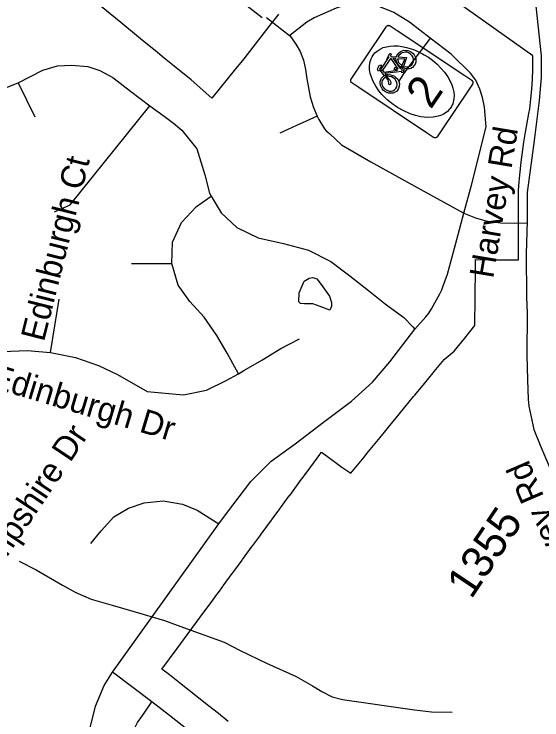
# Model space of a CAD drawing. Extents: x 1715610 to 1720914, y 798298 to 802505.
# Drawn here: x 1715843.1 to 1715888.3, y 799772 to 799832.4 of the extents above; entities that cross this region are included whole.
import ezdxf

# ---------------------------------------------------------------- set-up
doc = ezdxf.new("R2010")
doc.units = 0
doc.layers.add('Default', color=7, linetype='Continuous')

msp = doc.modelspace()

# ---------------------------------------------------------------- linework, layer by layer
at = {"layer": 'Default'}
for p, q in [((1715843.498, 799826.51), (1715844.92, 799823.586)), ((1715853.189, 799811.031), (1715856.623, 799811.039)), ((1715846.258, 799803.408), (1715846.988, 799807.974)), ((1715851.549, 799776.047), (1715860.659, 799788.734)), ((1715854.933, 799773.497), (1715851.549, 799776.047))]:
    msp.add_line(p, q, dxfattribs=at)
for points in [[(1715876.559, 799852.158), (1715873.018, 799854.904), (1715871.602, 799856.072), (1715871.096, 799856.41), (1715870.539, 799856.563), (1715870.048, 799856.378), (1715869.015, 799855.163), (1715864.188, 799848.936), (1715859.918, 799843.325), (1715857.646, 799840.515), (1715856.993, 799839.629), (1715856.823, 799839.026), (1715856.969, 799838.292), (1715857.158, 799837.776), (1715857.596, 799837.336), (1715858.861, 799836.269), (1715862.057, 799833.917), (1715864.379, 799832.097)], [(1715887.585, 799834.985), (1715887.96, 799831.478), (1715888.231, 799828.832), (1715888.24, 799826.949), (1715888.059, 799825.001), (1715887.645, 799821.58), (1715887.043, 799817.108), (1715887.035, 799814.677), (1715886.966, 799811.853), (1715886.98, 799808.164), (1715887.054, 799806.818), (1715887.014, 799803.184), (1715887.069, 799801.068), (1715887.121, 799799.414), (1715887.192, 799798.806), (1715887.621, 799796.808), (1715888.149, 799795.48), (1715889.133, 799793.201), (1715891.599, 799788.185)], [(1715886.642, 799820.577), (1715886.762, 799821.426), (1715886.899, 799822.273), (1715887.191, 799823.877), (1715887.258, 799824.293), (1715887.37, 799825.131), (1715887.452, 799825.969), (1715887.505, 799826.814), (1715887.529, 799827.655), (1715887.52, 799828.81), (1715880.178, 799834.08)], [(1715886.642, 799820.577), (1715886.762, 799821.426), (1715886.899, 799822.273), (1715887.191, 799823.877), (1715887.258, 799824.293), (1715887.37, 799825.131), (1715887.452, 799825.969), (1715887.505, 799826.814), (1715887.529, 799827.655), (1715887.52, 799828.81), (1715880.178, 799834.08)], [(1715865.775, 799832.394), (1715865.709, 799832.311), (1715865.027, 799831.433), (1715862.788, 799828.567), (1715862.536, 799828.245), (1715862.075, 799827.696), (1715860.067, 799825.183), (1715858.278, 799826.763), (1715856.833, 799827.94), (1715855.984, 799828.632), (1715855.408, 799829.1), (1715853.96, 799830.281), (1715852.268, 799831.66), (1715850.585, 799833.031)], [(1715865.775, 799832.394), (1715865.709, 799832.311), (1715865.027, 799831.433), (1715862.788, 799828.567), (1715862.536, 799828.245), (1715862.075, 799827.696), (1715860.067, 799825.183), (1715858.278, 799826.763), (1715856.833, 799827.94), (1715855.984, 799828.632), (1715855.408, 799829.1), (1715853.96, 799830.281), (1715852.268, 799831.66), (1715850.585, 799833.031)], [(1715878.748, 799830.326), (1715876.976, 799831.699), (1715875.637, 799832.526), (1715874.152, 799833.131), (1715873.227, 799833.256), (1715872.14, 799833.254), (1715871.393, 799833.126), (1715870.693, 799832.911), (1715868.815, 799832.08), (1715868.19, 799831.713), (1715866.72, 799830.548)], [(1715864.75, 799832.102), (1715866.702, 799830.573), (1715866.72, 799830.548)], [(1715866.72, 799830.548), (1715867.258, 799829.831), (1715867.629, 799829.184), (1715867.914, 799828.437), (1715868.071, 799827.645), (1715868.199, 799826.843), (1715868.339, 799826.065), (1715868.486, 799825.312), (1715868.757, 799824.385), (1715869.066, 799823.662)], [(1715878.748, 799830.326), (1715878.345, 799829.778), (1715877.811, 799829.072), (1715877.353, 799828.489), (1715876.892, 799827.875), (1715876.466, 799827.264), (1715876.064, 799826.643)], [(1715881.627, 799815.333), (1715882.276, 799817.751), (1715883.539, 799822.736), (1715883.392, 799824.424), (1715883.231, 799825.239), (1715883.005, 799825.975), (1715882.643, 799826.725), (1715882.193, 799827.33), (1715880.533, 799828.955), (1715878.748, 799830.326)], [(1715843.498, 799826.51), (1715845.61, 799827.603), (1715846.865, 799827.957), (1715848.037, 799828.027), (1715849.445, 799827.902), (1715850.482, 799827.555), (1715851.585, 799826.954), (1715853.101, 799825.802), (1715854.741, 799824.547)], [(1715838.111, 799825.072), (1715840.042, 799825.389), (1715842.115, 799825.964), (1715843.498, 799826.51)], [(1715846.609, 799815.458), (1715847.925, 799816.059), (1715854.741, 799824.547)], [(1715854.741, 799824.547), (1715855.99, 799823.652), (1715856.769, 799823.052), (1715857.483, 799822.457), (1715858.768, 799820.857), (1715859.464, 799818.632), (1715859.865, 799817.044), (1715860.014, 799816.794)], [(1715869.066, 799823.662), (1715868.12, 799823.212), (1715867.296, 799822.838), (1715866.556, 799822.502), (1715865.892, 799822.197)], [(1715869.066, 799823.662), (1715869.214, 799823.36), (1715869.692, 799822.559), (1715869.836, 799822.397), (1715870.121, 799822.154), (1715871.155, 799821.2), (1715873.651, 799819.739), (1715876.813, 799817.985), (1715879.345, 799816.589), (1715881.627, 799815.333)], [(1715861.464, 799771.825), (1715860.625, 799772.485), (1715859.779, 799773.156), (1715858.946, 799773.811), (1715858.112, 799774.471), (1715857.279, 799775.13), (1715856.433, 799775.797), (1715855.793, 799776.305), (1715856.438, 799777.181), (1715857.084, 799778.061), (1715858.967, 799780.625), (1715859.067, 799780.757), (1715860.139, 799782.216), (1715860.405, 799782.577), (1715860.623, 799782.873), (1715860.988, 799783.375), (1715861.026, 799783.428), (1715861.81, 799784.493), (1715861.849, 799784.546), (1715862, 799784.752), (1715862.192, 799785.013), (1715862.651, 799785.638), (1715862.69, 799785.69), (1715863.524, 799786.824), (1715863.561, 799786.874), (1715864.159, 799787.687), (1715864.336, 799787.929), (1715864.373, 799787.98), (1715865.168, 799789.06), (1715865.206, 799789.113), (1715865.907, 799790.067), (1715865.944, 799790.117), (1715866.686, 799791.126), (1715866.711, 799791.161), (1715866.723, 799791.176), (1715867.745, 799792.566), (1715867.782, 799792.617), (1715868.526, 799793.627), (1715869.304, 799794.687), (1715869.343, 799794.739), (1715869.443, 799794.871), (1715869.955, 799794.499), (1715871.189, 799793.601), (1715871.94, 799793.069), (1715873.082, 799794.461), (1715873.33, 799794.763), (1715874.455, 799796.137), (1715875.556, 799797.481), (1715875.724, 799797.685), (1715876.572, 799798.721), (1715877.32, 799799.633), (1715877.419, 799799.754), (1715878.244, 799800.759), (1715878.985, 799801.663), (1715879.088, 799801.79), (1715879.933, 799802.821), (1715880.807, 799803.528), (1715881.696, 799804.651), (1715882.556, 799805.737), (1715882.559, 799806.003), (1715882.586, 799807.843), (1715882.629, 799810.91), (1715882.635, 799811.367), (1715884.007, 799811.355), (1715886.305, 799811.335), (1715886.315, 799817.298), (1715886.366, 799818.017), (1715886.443, 799818.872), (1715886.535, 799819.726), (1715886.642, 799820.577)], [(1715861.464, 799771.825), (1715860.625, 799772.485), (1715859.779, 799773.156), (1715858.946, 799773.811), (1715858.112, 799774.471), (1715857.279, 799775.13), (1715856.433, 799775.797), (1715855.793, 799776.305), (1715856.438, 799777.181), (1715857.084, 799778.061), (1715858.967, 799780.625), (1715859.067, 799780.757), (1715860.139, 799782.216), (1715860.405, 799782.577), (1715860.623, 799782.873), (1715860.988, 799783.375), (1715861.026, 799783.428), (1715861.81, 799784.493), (1715861.849, 799784.546), (1715862, 799784.752), (1715862.192, 799785.013), (1715862.651, 799785.638), (1715862.69, 799785.69), (1715863.524, 799786.824), (1715863.561, 799786.874), (1715864.159, 799787.687), (1715864.336, 799787.929), (1715864.373, 799787.98), (1715865.168, 799789.06), (1715865.206, 799789.113), (1715865.907, 799790.067), (1715865.944, 799790.117), (1715866.686, 799791.126), (1715866.711, 799791.161), (1715866.723, 799791.176), (1715867.745, 799792.566), (1715867.782, 799792.617), (1715868.526, 799793.627), (1715869.304, 799794.687), (1715869.343, 799794.739), (1715869.443, 799794.871), (1715869.955, 799794.499), (1715871.189, 799793.601), (1715871.94, 799793.069), (1715873.082, 799794.461), (1715873.33, 799794.763), (1715874.455, 799796.137), (1715875.556, 799797.481), (1715875.724, 799797.685), (1715876.572, 799798.721), (1715877.32, 799799.633), (1715877.419, 799799.754), (1715878.244, 799800.759), (1715878.985, 799801.663), (1715879.088, 799801.79), (1715879.933, 799802.821), (1715880.807, 799803.528), (1715881.696, 799804.651), (1715882.556, 799805.737), (1715882.559, 799806.003), (1715882.586, 799807.843), (1715882.629, 799810.91), (1715882.635, 799811.367), (1715884.007, 799811.355), (1715886.305, 799811.335), (1715886.315, 799817.298), (1715886.366, 799818.017), (1715886.443, 799818.872), (1715886.535, 799819.726), (1715886.642, 799820.577)], [(1715856.623, 799811.039), (1715856.687, 799812.861), (1715857.462, 799814.541), (1715858.748, 799815.911), (1715859.729, 799816.596), (1715860.014, 799816.794)], [(1715860.014, 799816.794), (1715860.857, 799815.376), (1715862.191, 799814.107), (1715864.021, 799813.245), (1715866.187, 799812.738), (1715868.333, 799812.168), (1715870.235, 799811.209), (1715871.873, 799809.986), (1715873.467, 799808.723), (1715874.899, 799807.568), (1715876.493, 799806.409), (1715877.248, 799805.616), (1715877.433, 799805.41)], [(1715877.433, 799805.41), (1715878.366, 799806.455), (1715878.631, 799806.787), (1715878.862, 799807.153), (1715879.577, 799808.435), (1715879.748, 799808.784), (1715879.84, 799809.027), (1715880.218, 799810.119), (1715881.019, 799813.093), (1715881.627, 799815.333)], [(1715881.627, 799815.333), (1715882.627, 799814.932), (1715883.508, 799814.682), (1715884.756, 799814.511), (1715886, 799814.496), (1715886.982, 799814.526)], [(1715862.333, 799801.6), (1715861.365, 799803.347), (1715860.477, 799804.861), (1715859.404, 799806.433), (1715858.184, 799807.789), (1715857.183, 799809.169), (1715856.623, 799811.039)], [(1715870.166, 799807.043), (1715869.325, 799807.354), (1715868.69, 799807.58), (1715868.001, 799807.574), (1715867.652, 799807.604), (1715867.496, 799807.762), (1715867.54, 799808.521), (1715867.951, 799809.508), (1715868.399, 799809.777), (1715868.702, 799809.837), (1715869.039, 799809.713), (1715869.406, 799809.247), (1715869.834, 799808.639), (1715870.131, 799808.225), (1715870.295, 799807.692), (1715870.293, 799807.382), (1715870.166, 799807.043)], [(1715870.166, 799807.043), (1715869.325, 799807.354), (1715868.69, 799807.58), (1715868.001, 799807.574), (1715867.652, 799807.604), (1715867.496, 799807.762), (1715867.54, 799808.521), (1715867.951, 799809.508), (1715868.399, 799809.777), (1715868.702, 799809.837), (1715869.039, 799809.713), (1715869.406, 799809.247), (1715870.131, 799808.225), (1715870.295, 799807.692), (1715870.293, 799807.382), (1715870.166, 799807.043)], [(1715860.659, 799788.734), (1715861.319, 799789.618), (1715863.392, 799792.359), (1715865.147, 799794.106), (1715867.199, 799795.582), (1715869.609, 799797.436), (1715872.02, 799799.232), (1715873.819, 799800.864), (1715875.28, 799802.615), (1715877.433, 799805.41)], [(1715862.333, 799801.6), (1715862.81, 799801.873), (1715864.351, 799802.758), (1715865.952, 799803.745), (1715867.565, 799804.576)], [(1715838.243, 799802.606), (1715838.311, 799802.626), (1715840.122, 799803.168), (1715842.183, 799803.499), (1715844.268, 799803.572), (1715846.258, 799803.408)], [(1715846.258, 799803.408), (1715848.387, 799802.974), (1715850.36, 799802.298), (1715851.977, 799801.534), (1715854.538, 799800.065), (1715857.628, 799799.783), (1715859.602, 799800.199), (1715861.279, 799801.013), (1715862.333, 799801.6)], [(1715849.714, 799787.057), (1715850.578, 799788.153), (1715851.68, 799789.34), (1715852.936, 799790.076), (1715854.258, 799790.532), (1715855.893, 799790.707), (1715857.561, 799790.416), (1715858.795, 799789.901), (1715860.659, 799788.734)], [(1715843.566, 799785.536), (1715845.02, 799784.81), (1715847.272, 799783.479), (1715848.422, 799782.849), (1715849.72, 799782.281), (1715851.537, 799781.778), (1715853.294, 799781.263), (1715856.011, 799780.458), (1715857.959, 799779.761), (1715861.121, 799778.605), (1715862.475, 799777.887), (1715864.745, 799776.813), (1715867.278, 799775.66), (1715868.68, 799774.861), (1715869.46, 799774.382), (1715870.36, 799773.924), (1715871.251, 799773.687), (1715877.398, 799772.809), (1715878.867, 799772.647), (1715880.626, 799772.602)], [(1715850.734, 799757.218), (1715850.559, 799759.171), (1715850.308, 799760.644), (1715849.649, 799763.11), (1715849.277, 799765.522), (1715849.136, 799767.988), (1715849.51, 799770.692), (1715850.115, 799773.137), (1715850.84, 799774.885), (1715851.549, 799776.047)], [(1715852.97, 799764.755), (1715852.87, 799765.283), (1715852.795, 799765.87), (1715852.734, 799766.447), (1715852.7, 799767.052), (1715852.686, 799767.667), (1715852.693, 799767.986), (1715852.705, 799768.311), (1715852.726, 799768.683), (1715852.78, 799769.059), (1715852.925, 799769.82), (1715853.157, 799770.567), (1715853.402, 799771.149), (1715853.706, 799771.718), (1715854.068, 799772.234), (1715854.331, 799772.608), (1715854.933, 799773.497)], [(1715859.683, 799769.749), (1715856.435, 799772.315), (1715854.933, 799773.497)]]:
    msp.add_lwpolyline(points, dxfattribs=at)
for points in [[(1715871.97, 799826.805), (1715871.979, 799826.82), (1715872.378, 799827.417), (1715874.597, 799830.731), (1715874.996, 799831.328), (1715875.013, 799831.348), (1715875.022, 799831.359), (1715875.034, 799831.37), (1715875.047, 799831.381), (1715875.06, 799831.391), (1715875.088, 799831.407), (1715875.102, 799831.413), (1715875.118, 799831.419), (1715875.138, 799831.425), (1715875.167, 799831.429), (1715875.189, 799831.431), (1715875.201, 799831.43), (1715875.21, 799831.429), (1715875.222, 799831.428), (1715875.232, 799831.427), (1715875.243, 799831.425), (1715875.26, 799831.42), (1715875.279, 799831.414), (1715875.297, 799831.405), (1715875.304, 799831.402), (1715875.312, 799831.398), (1715875.917, 799830.993), (1715881.699, 799827.123), (1715882.297, 799826.723), (1715882.317, 799826.707), (1715882.327, 799826.697), (1715882.339, 799826.685), (1715882.35, 799826.673), (1715882.359, 799826.659), (1715882.375, 799826.631), (1715882.381, 799826.617), (1715882.387, 799826.602), (1715882.393, 799826.581), (1715882.395, 799826.568), (1715882.398, 799826.552), (1715882.398, 799826.543), (1715882.399, 799826.53), (1715882.399, 799826.519), (1715882.398, 799826.51), (1715882.397, 799826.497), (1715882.393, 799826.476), (1715882.389, 799826.46), (1715882.382, 799826.44), (1715882.378, 799826.431), (1715882.374, 799826.422), (1715882.37, 799826.415), (1715882.366, 799826.408), (1715882.36, 799826.398), (1715881.961, 799825.801), (1715879.743, 799822.488), (1715879.344, 799821.891), (1715879.335, 799821.881), (1715879.328, 799821.871), (1715879.318, 799821.861), (1715879.306, 799821.849), (1715879.294, 799821.838), (1715879.28, 799821.829), (1715879.265, 799821.82), (1715879.252, 799821.813), (1715879.238, 799821.807), (1715879.223, 799821.801), (1715879.213, 799821.798), (1715879.203, 799821.795), (1715879.195, 799821.793), (1715879.182, 799821.792), (1715879.17, 799821.79), (1715879.157, 799821.789), (1715879.145, 799821.789), (1715879.134, 799821.79), (1715879.121, 799821.791), (1715879.109, 799821.792), (1715879.097, 799821.795), (1715879.09, 799821.796), (1715879.083, 799821.798), (1715879.078, 799821.8), (1715879.073, 799821.801), (1715879.068, 799821.803), (1715879.063, 799821.805), (1715879.058, 799821.807), (1715879.053, 799821.809), (1715879.048, 799821.811), (1715879.044, 799821.814), (1715879.04, 799821.816), (1715879.034, 799821.818), (1715879.023, 799821.825), (1715878.423, 799822.226), (1715872.64, 799826.097), (1715872.043, 799826.497), (1715872.023, 799826.513), (1715872.013, 799826.522), (1715872.001, 799826.534), (1715871.99, 799826.547), (1715871.981, 799826.56), (1715871.965, 799826.588), (1715871.958, 799826.602), (1715871.952, 799826.618), (1715871.947, 799826.638), (1715871.942, 799826.668), (1715871.941, 799826.69), (1715871.941, 799826.701), (1715871.942, 799826.71), (1715871.943, 799826.722), (1715871.945, 799826.732), (1715871.947, 799826.743), (1715871.951, 799826.76), (1715871.958, 799826.78), (1715871.966, 799826.797)], [(1715880.499, 799824.38), (1715880.44, 799824.299), (1715880.379, 799824.224), (1715880.228, 799824.064), (1715880.018, 799823.911), (1715879.881, 799823.832), (1715879.763, 799823.772), (1715879.624, 799823.716), (1715879.421, 799823.643), (1715879.004, 799823.563), (1715878.515, 799823.537), (1715877.954, 799823.603), (1715877.477, 799823.706), (1715877.044, 799823.859), (1715876.418, 799824.13), (1715875.955, 799824.391), (1715875.738, 799824.533), (1715875.584, 799824.641), (1715875.476, 799824.722), (1715875.315, 799824.846), (1715875.074, 799825.045), (1715874.842, 799825.27), (1715874.696, 799825.42), (1715874.618, 799825.507), (1715874.476, 799825.673), (1715874.354, 799825.821), (1715874.079, 799826.212), (1715873.862, 799826.614), (1715873.711, 799826.998), (1715873.614, 799827.313), (1715873.558, 799827.65), (1715873.558, 799827.884), (1715873.564, 799828), (1715873.577, 799828.129), (1715873.609, 799828.333), (1715873.687, 799828.551), (1715873.773, 799828.738), (1715873.863, 799828.88), (1715874.015, 799829.063), (1715874.208, 799829.231), (1715874.467, 799829.398), (1715874.729, 799829.518), (1715874.996, 799829.594), (1715875.325, 799829.653), (1715875.636, 799829.673), (1715875.991, 799829.66), (1715876.323, 799829.625), (1715876.721, 799829.544), (1715877.114, 799829.427), (1715877.471, 799829.293), (1715877.807, 799829.146), (1715878.088, 799828.998), (1715878.242, 799828.909), (1715878.596, 799828.697), (1715878.953, 799828.434), (1715879.347, 799828.099), (1715879.669, 799827.773), (1715879.976, 799827.414), (1715880.246, 799827.029), (1715880.452, 799826.652), (1715880.587, 799826.338), (1715880.687, 799826.04), (1715880.763, 799825.695), (1715880.787, 799825.409), (1715880.77, 799825.126), (1715880.719, 799824.86), (1715880.668, 799824.708), (1715880.631, 799824.625), (1715880.601, 799824.554), (1715880.559, 799824.481)], [(1715875.047, 799828.54), (1715875.287, 799829.01), (1715875.342, 799829.021), (1715875.392, 799828.949), (1715875.353, 799828.82), (1715875.393, 799828.752), (1715875.824, 799828.728), (1715875.988, 799828.998), (1715876.195, 799829.196), (1715876.486, 799829.296), (1715876.705, 799829.288), (1715876.82, 799829.279), (1715876.983, 799829.218), (1715877.135, 799829.126), (1715877.277, 799829.004), (1715877.372, 799828.893), (1715877.452, 799828.744), (1715877.504, 799828.618), (1715877.521, 799828.43), (1715877.511, 799828.277), (1715877.447, 799828.1), (1715877.387, 799828.001), (1715877.227, 799827.827), (1715877.08, 799827.745), (1715876.988, 799827.718), (1715876.808, 799827.703), (1715876.658, 799827.716), (1715876.381, 799827.779), (1715876.262, 799827.832), (1715876.447, 799827.901), (1715876.696, 799827.887), (1715876.868, 799827.88), (1715877, 799827.931), (1715877.16, 799828.038), (1715877.236, 799828.146), (1715877.302, 799828.316), (1715877.315, 799828.503), (1715877.285, 799828.666), (1715877.208, 799828.83), (1715877.044, 799828.977), (1715876.893, 799829.071), (1715876.749, 799829.12), (1715876.597, 799829.13), (1715876.476, 799829.116), (1715876.322, 799829.063), (1715876.22, 799828.982), (1715876.074, 799828.836), (1715875.984, 799828.726), (1715876.73, 799828.685), (1715876.447, 799827.901), (1715876.262, 799827.832), (1715876.564, 799828.524), (1715875.949, 799828.563), (1715876.022, 799828.256), (1715876.323, 799827.981), (1715876.262, 799827.832), (1715876.125, 799827.933), (1715875.949, 799828.132), (1715875.868, 799828.329), (1715875.8, 799828.578), (1715875.551, 799828.616), (1715876.19, 799827.696), (1715876.262, 799827.835), (1715876.381, 799827.779), (1715876.297, 799827.615), (1715876.412, 799827.585), (1715876.523, 799827.643), (1715876.422, 799827.382), (1715876.314, 799827.373), (1715876.324, 799827.484), (1715874.861, 799827.294), (1715874.928, 799827.205), (1715875.153, 799827.217), (1715875.349, 799827.195), (1715875.536, 799827.14), (1715875.688, 799827.076), (1715875.815, 799826.971), (1715875.968, 799826.814), (1715876.07, 799826.617), (1715876.108, 799826.412), (1715876.101, 799826.213), (1715876.027, 799826.011), (1715875.953, 799825.878), (1715875.85, 799825.76), (1715875.566, 799825.629), (1715875.435, 799825.611), (1715875.179, 799825.633), (1715874.915, 799825.745), (1715874.747, 799825.854), (1715874.628, 799825.995), (1715874.539, 799826.149), (1715874.493, 799826.289), (1715874.459, 799826.471), (1715874.463, 799826.608), (1715874.508, 799826.757), (1715874.581, 799826.891), (1715874.797, 799827.147), (1715874.988, 799827.111), (1715875.273, 799826.798), (1715875.38, 799826.567), (1715875.348, 799826.357), (1715875.243, 799826.337), (1715875.153, 799826.77), (1715874.942, 799826.992), (1715874.877, 799826.951), (1715874.77, 799826.867), (1715874.649, 799826.696), (1715874.614, 799826.578), (1715874.602, 799826.391), (1715874.684, 799826.151), (1715874.821, 799825.978), (1715875.03, 799825.872), (1715875.243, 799825.8), (1715875.401, 799825.786), (1715875.534, 799825.829), (1715875.703, 799825.907), (1715875.802, 799826.01), (1715875.89, 799826.161), (1715875.923, 799826.342), (1715875.883, 799826.546), (1715875.787, 799826.722), (1715875.712, 799826.836), (1715875.587, 799826.937), (1715875.431, 799827.014), (1715875.222, 799827.056), (1715874.797, 799827.147), (1715874.496, 799827.549), (1715874.664, 799827.578), (1715874.783, 799827.421), (1715875.934, 799827.583), (1715875.83, 799827.625), (1715875.67, 799827.634), (1715875.665, 799827.682), (1715875.789, 799827.867), (1715875.897, 799827.743), (1715876.004, 799827.699), (1715875.371, 799828.618), (1715874.664, 799827.578), (1715874.496, 799827.549), (1715874.288, 799827.515), (1715874.235, 799827.699), (1715874.385, 799827.999), (1715874.545, 799828.051), (1715874.583, 799827.941), (1715874.452, 799827.785), (1715874.401, 799827.653), (1715874.441, 799827.663), (1715874.481, 799827.721), (1715874.522, 799827.656), (1715875.248, 799828.721), (1715875.227, 799828.745)]]:
    msp.add_lwpolyline(points, close=True, dxfattribs=at)

# ---------------------------------------------------------------- texts
for s, height, rotation, p in [('2', 2.773, 56.20506, (1715878.798, 799824.167)), ('Harvey Rd', 2.0663, 80.54638, (1715884.127, 799809.688)), ('Edinburgh Ct', 2.06625, 75.86934, (1715845.689, 799804.268)), ('Edinburgh Dr', 2.06625, 343.29851, (1715840.96, 799800.49)), ('New Hampshire Dr', 2.06625, 56.20506, (1715836.576, 799776.959)), ('Harvey Rd', 2.0663, 113.34384, (1715892.29, 799782.331)), ('1355', 2.7188, 56.20506, (1715882.251, 799782.215))]:
    msp.add_text(s, height=height, rotation=rotation, dxfattribs=at).set_placement(p)

doc.saveas('drawing.dxf')
